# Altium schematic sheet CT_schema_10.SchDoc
size 281 x 153 mm
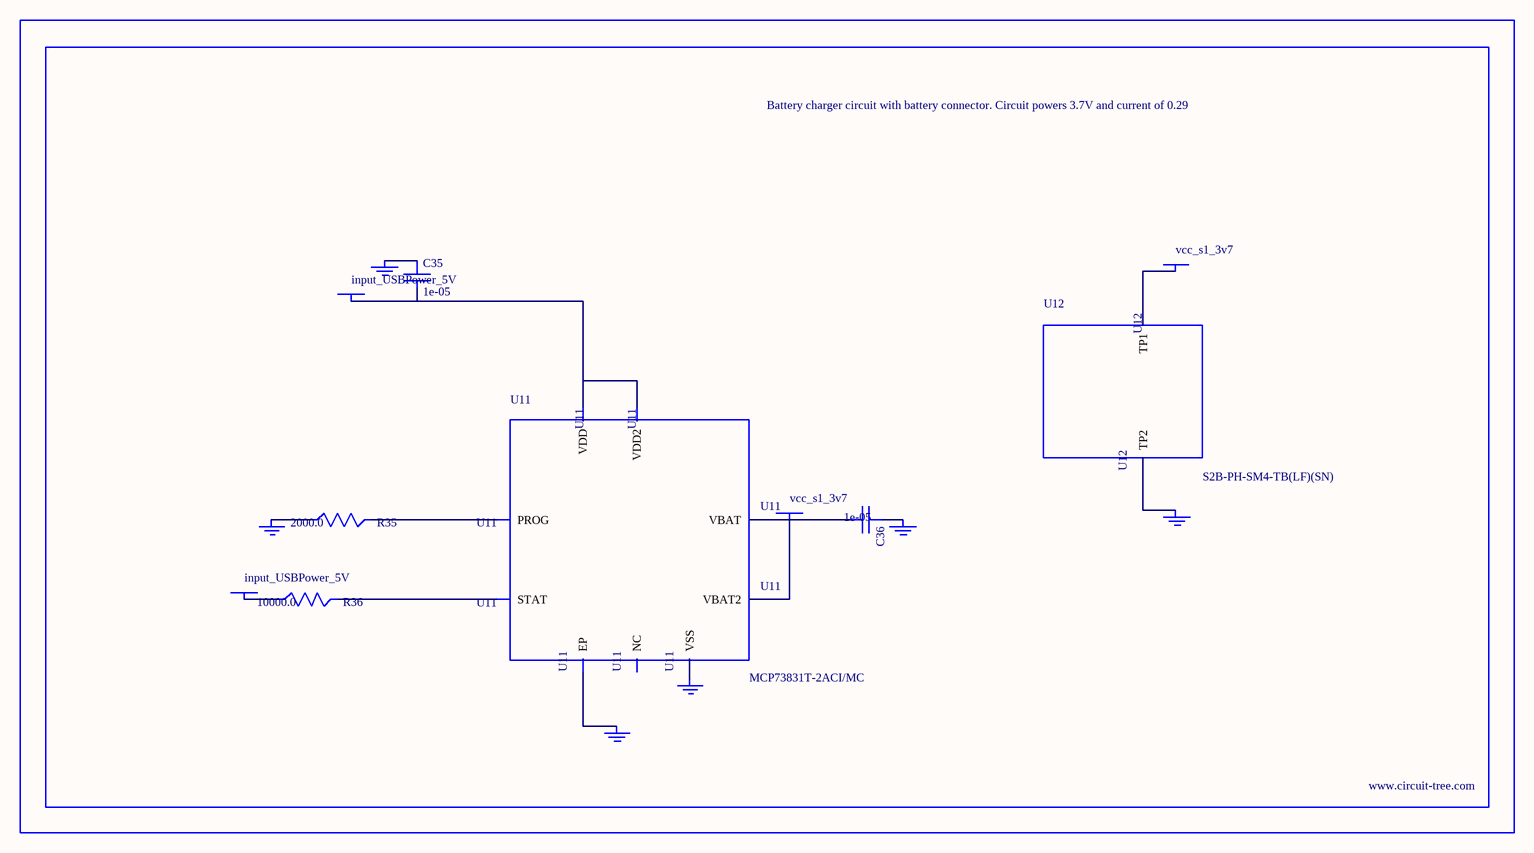
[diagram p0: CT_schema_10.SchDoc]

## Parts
BORDER9  (no value)
C35  1e-05  [C1206]
C36  1e-05  [C1206]
GND_INSTANCE_9_0  (no value)
GND_INSTANCE_9_1  (no value)
GND_INSTANCE_9_2  (no value)
GND_INSTANCE_9_3  (no value)
GND_INSTANCE_9_4  (no value)
GND_INSTANCE_9_5  (no value)
POWER_INSTANCE_9_0  input_USBPower_5V
POWER_INSTANCE_9_1  input_USBPower_5V
POWER_INSTANCE_9_2  vcc_s1_3v7
POWER_INSTANCE_9_3  vcc_s1_3v7
R35  2000.0  [R0603]
R36  10000.0  [R0603]
U11  MCP73831T-2ACI/MC  [DFN8_2X3MC]
U12  S2B-PH-SM4-TB(LF)(SN)  [JST-2-SMD]

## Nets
NetC35_1: C35.1 GND_INSTANCE_9_0.0(GND)
NetC35_2: C35.2 POWER_INSTANCE_9_0.0(PWR) U11.1(VDD) U11.2(VDD2)
NetC36_1: C36.1 GND_INSTANCE_9_1.0(GND)
NetC36_2: C36.2 POWER_INSTANCE_9_2.0(PWR) U11.3(VBAT) U11.4(VBAT2)
NetGND_INSTANCE_9_2_0: GND_INSTANCE_9_2.0(GND) R35.1
NetGND_INSTANCE_9_3_0: GND_INSTANCE_9_3.0(GND) U11.9(EP)
NetGND_INSTANCE_9_4_0: GND_INSTANCE_9_4.0(GND) U11.6(VSS)
NetGND_INSTANCE_9_5_0: GND_INSTANCE_9_5.0(GND) U12.2(TP2)
NetPOWER_INSTANCE_9_1_0: POWER_INSTANCE_9_1.0(PWR) R36.1
NetPOWER_INSTANCE_9_3_0: POWER_INSTANCE_9_3.0(PWR) U12.1(TP1)
NetR35_2: R35.2 U11.8(PROG)
NetR36_2: R36.2 U11.5(STAT)

Not connected (* = marked no-connect by the designer): U11 7(NC)

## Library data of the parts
BORDER9 = BORDER_PAGE9
C35 C36 = C1206C106K3RACTU
GND_INSTANCE_9_0-GND_INSTANCE_9_5 = GND
POWER_INSTANCE_9_0-POWER_INSTANCE_9_3 = PWR
R35 = RC0603JR-072KL
R36 = RC0603JR-0710KL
